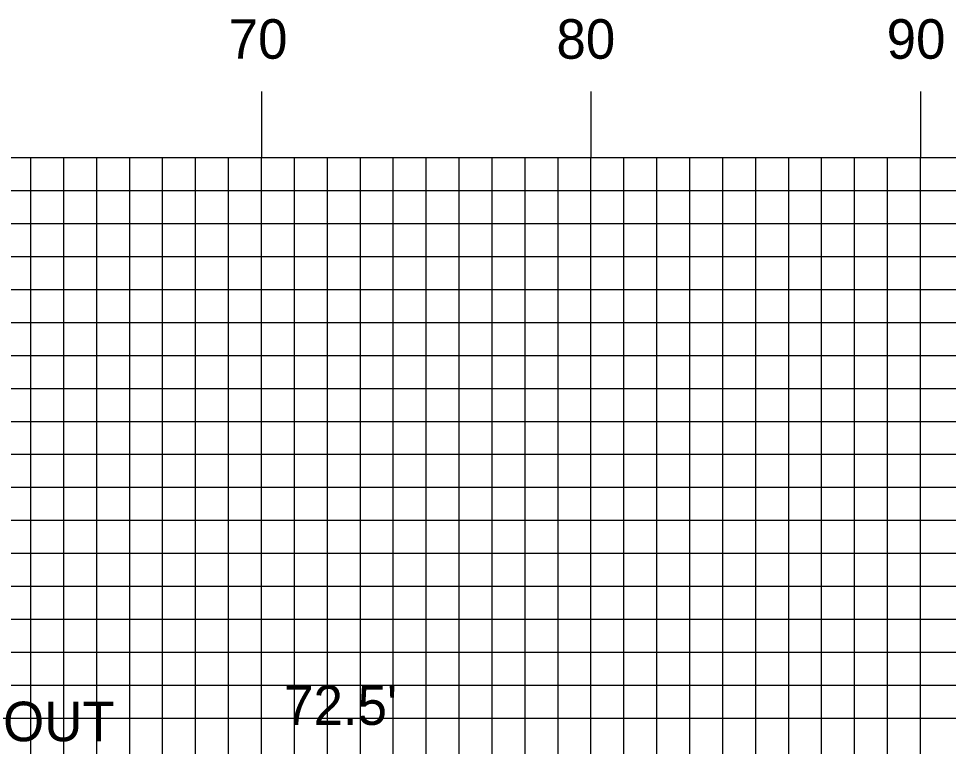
# Model space of a CAD drawing. Extents: x 1807045 to 1807388, y 442591 to 442811.
# Drawn here: x 1807273.39 to 1807301.61, y 442680.8 to 442702.88 of the extents above; entities that cross this region are included whole.
import ezdxf

# ---------------------------------------------------------------- set-up
doc = ezdxf.new("R2010")
doc.units = 0
for name, color, linetype in [('ANNOTATION', 7, 'Continuous'), ('D_Text_Standard', 7, 'Continuous'), ('H_V ANNOTATION', 7, 'Continuous'), ('MAJOR', 7, 'Continuous'), ('MINOR', 7, 'Continuous')]:
    doc.layers.add(name, color=color, linetype=linetype)

msp = doc.modelspace()

# ---------------------------------------------------------------- linework, layer by layer
at = {"layer": 'MAJOR'}
for p, q in [((1807280.759, 442700.669), (1807280.759, 442698.665)), ((1807290.759, 442700.669), (1807290.759, 442698.665)), ((1807300.759, 442700.669), (1807300.759, 442698.665)), ((1807070.759, 442698.665), (1807350.759, 442698.665)), ((1807070.759, 442698.665), (1807350.759, 442698.665)), ((1807280.759, 442663.665), (1807280.759, 442698.665)), ((1807290.759, 442663.665), (1807290.759, 442698.665)), ((1807300.759, 442663.665), (1807300.759, 442698.665)), ((1807070.759, 442693.665), (1807350.759, 442693.665)), ((1807070.759, 442688.665), (1807350.759, 442688.665)), ((1807070.759, 442683.665), (1807350.759, 442683.665))]:
    msp.add_line(p, q, dxfattribs=at)
at = {"layer": 'MINOR'}
for p, q in [((1807273.759, 442663.665), (1807273.759, 442698.665)), ((1807274.759, 442663.665), (1807274.759, 442698.665)), ((1807275.759, 442663.665), (1807275.759, 442698.665)), ((1807276.759, 442663.665), (1807276.759, 442698.665)), ((1807277.759, 442663.665), (1807277.759, 442698.665)), ((1807278.759, 442663.665), (1807278.759, 442698.665)), ((1807279.759, 442663.665), (1807279.759, 442698.665)), ((1807281.759, 442663.665), (1807281.759, 442698.665)), ((1807282.759, 442663.665), (1807282.759, 442698.665)), ((1807283.759, 442663.665), (1807283.759, 442698.665)), ((1807284.759, 442663.665), (1807284.759, 442698.665)), ((1807285.759, 442663.665), (1807285.759, 442698.665)), ((1807286.759, 442663.665), (1807286.759, 442698.665)), ((1807287.759, 442663.665), (1807287.759, 442698.665)), ((1807288.759, 442663.665), (1807288.759, 442698.665)), ((1807289.759, 442663.665), (1807289.759, 442698.665)), ((1807291.759, 442663.665), (1807291.759, 442698.665)), ((1807292.759, 442663.665), (1807292.759, 442698.665)), ((1807293.759, 442663.665), (1807293.759, 442698.665)), ((1807294.759, 442663.665), (1807294.759, 442698.665)), ((1807295.759, 442663.665), (1807295.759, 442698.665)), ((1807296.759, 442663.665), (1807296.759, 442698.665)), ((1807297.759, 442663.665), (1807297.759, 442698.665)), ((1807298.759, 442663.665), (1807298.759, 442698.665)), ((1807299.759, 442663.665), (1807299.759, 442698.665)), ((1807070.759, 442697.665), (1807350.759, 442697.665)), ((1807070.759, 442696.665), (1807350.759, 442696.665)), ((1807070.759, 442695.665), (1807350.759, 442695.665)), ((1807070.759, 442694.665), (1807350.759, 442694.665)), ((1807070.759, 442692.665), (1807350.759, 442692.665)), ((1807070.759, 442691.665), (1807350.759, 442691.665)), ((1807070.759, 442690.665), (1807350.759, 442690.665)), ((1807070.759, 442689.665), (1807350.759, 442689.665)), ((1807070.759, 442687.665), (1807350.759, 442687.665)), ((1807070.759, 442686.665), (1807350.759, 442686.665)), ((1807070.759, 442685.665), (1807350.759, 442685.665)), ((1807070.759, 442684.665), (1807350.759, 442684.665)), ((1807070.759, 442682.665), (1807350.759, 442682.665)), ((1807070.759, 442681.665), (1807350.759, 442681.665))]:
    msp.add_line(p, q, dxfattribs=at)

# ---------------------------------------------------------------- texts
at = {"layer": 'ANNOTATION'}
msp.add_text('OUT', height=1.2, dxfattribs=at).set_placement((1807272.916, 442680.961))
at = {"layer": 'D_Text_Standard'}
msp.add_text("72.5'", height=1.2, dxfattribs=at).set_placement((1807281.445, 442681.456))
at = {"layer": 'H_V ANNOTATION'}
for s, p in [('70', (1807279.763, 442701.665)), ('80', (1807289.71, 442701.665)), ('90', (1807299.731, 442701.665))]:
    msp.add_text(s, height=1.2, dxfattribs=at).set_placement(p)

doc.saveas('drawing.dxf')
